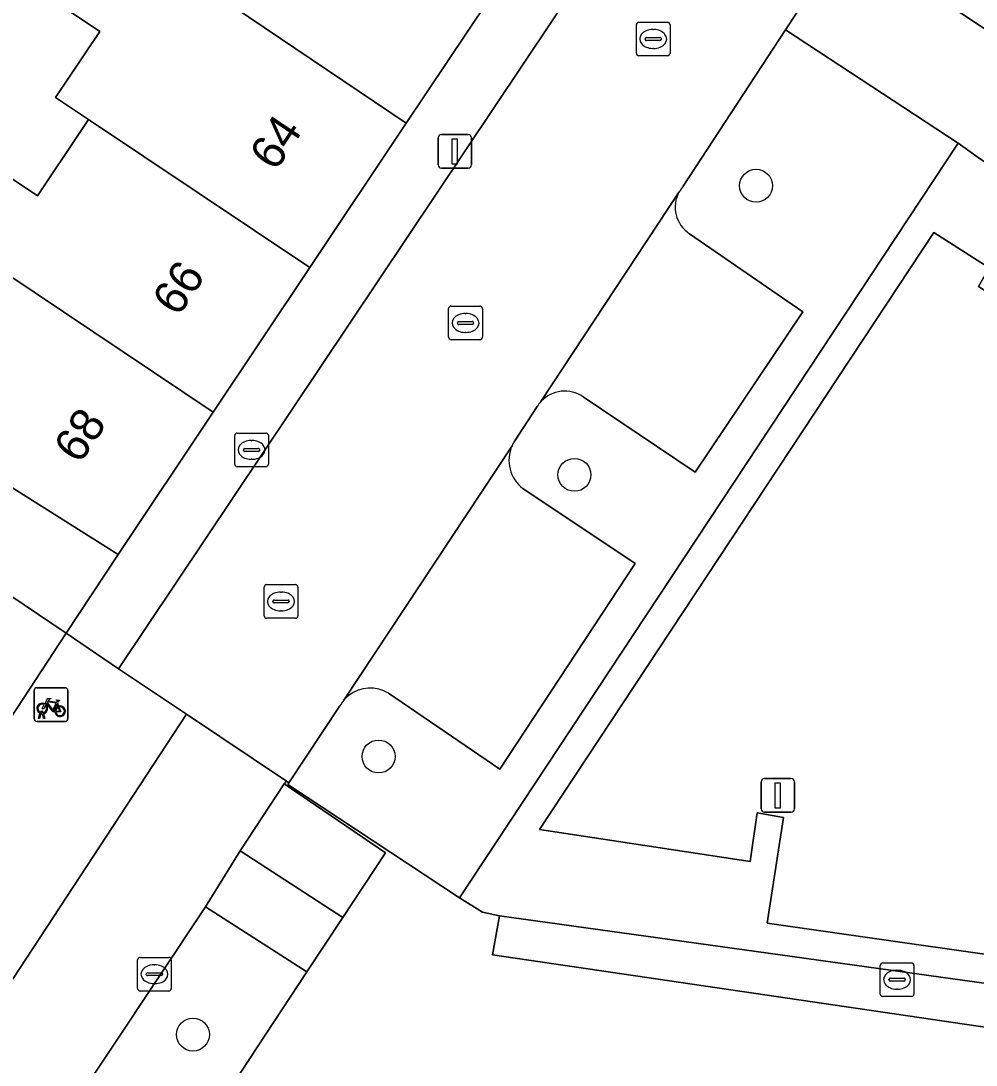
# Model space of a CAD drawing. Extents: x 159279 to 160377, y 384531 to 385888.
# Drawn here: x 159929.07 to 159957.43, y 384726.45 to 384757.45 of the extents above; entities that cross this region are included whole.
import ezdxf

# ---------------------------------------------------------------- set-up
doc = ezdxf.new("R2010")
doc.units = 0
for name, color, linetype in [('IMGEO_Boom', 7, 'Continuous'), ('IMGEO_Brandkraan', 7, 'Continuous'), ('IMGEO_Erf', 7, 'Continuous'), ('IMGEO_Fietsenrek', 7, 'Continuous'), ('IMGEO_Groenvoorziening', 7, 'Continuous'), ('IMGEO_Kolk', 7, 'Continuous'), ('IMGEO_Lichtmast', 7, 'Continuous'), ('IMGEO_Pand', 7, 'Continuous'), ('IMGEO_Pand_nummerreeks', 7, 'Continuous'), ('IMGEO_Parkeervlak_open', 7, 'Continuous'), ('IMGEO_Rijbaan_lokaal_open', 7, 'Continuous'), ('IMGEO_Terreindeel_gesloten', 7, 'Continuous'), ('IMGEO_Voetpad_halfverhard', 7, 'Continuous'), ('IMGEO_Voetpad_open', 7, 'Continuous')]:
    doc.layers.add(name, color=color, linetype=linetype)

msp = doc.modelspace()

# ---------------------------------------------------------------- linework, layer by layer
at = {"layer": 'IMGEO_Boom'}
for centre in [(159950.897, 384752.557), (159945.504, 384743.972), (159939.689, 384735.609), (159934.177, 384727.353)]:
    msp.add_circle(centre, 0.489, dxfattribs=at)
at = {"layer": 'IMGEO_Brandkraan'}
for p, q in [((159935.415, 384744.287), (159935.415, 384745.139)), ((159935.49, 384745.213), (159936.342, 384745.213)), ((159936.416, 384745.139), (159936.416, 384744.287)), ((159935.903, 384744.993), (159935.928, 384744.993)), ((159935.674, 384744.707), (159935.674, 384744.719)), ((159936.112, 384744.67), (159935.714, 384744.67)), ((159935.717, 384744.756), (159936.115, 384744.756)), ((159936.158, 384744.719), (159936.158, 384744.707)), ((159936.342, 384744.213), (159935.49, 384744.213)), ((159935.926, 384744.433), (159935.901, 384744.433))]:
    msp.add_line(p, q, dxfattribs=at)
for points in [[(159935.415, 384744.287), (159935.415, 384745.139)], [(159935.49, 384745.213), (159936.342, 384745.213)], [(159936.416, 384745.139), (159936.416, 384744.287)], [(159936.342, 384744.213), (159935.49, 384744.213)]]:
    msp.add_lwpolyline(points, dxfattribs=at)
for centre, radius, start, end in [((159935.492, 384745.137), 0.0765, 91.552, 178.448), ((159935.492, 384745.137), 0.0765, 91.552, 178.448), ((159936.34, 384745.137), 0.0765, 1.552, 88.448), ((159936.34, 384745.137), 0.0765, 1.552, 88.448), ((159935.714, 384744.716), 0.0403, 85.8775, 175.7526), ((159935.711, 384744.706), 0.0366, 178.938, 274.7102), ((159936.115, 384744.713), 0.043, 264.8664, 352.4533), ((159936.119, 384744.718), 0.0386, 1.7309, 96.639), ((159935.492, 384744.289), 0.0765, 181.552, 268.448), ((159935.492, 384744.289), 0.0765, 181.552, 268.448), ((159936.34, 384744.289), 0.0765, 271.552, 358.448), ((159936.34, 384744.289), 0.0765, 271.552, 358.448)]:
    msp.add_arc(centre, radius, start, end, dxfattribs=at)
for centre, major_axis, ratio, start_param, end_param in [((159935.902, 384744.713), (-0.387, 0.002), 0.722429, 4.712389, 7.853982), ((159935.927, 384744.713), (-0.39, 0.002), 0.717154, 1.570796, 4.712389)]:
    msp.add_ellipse(centre, major_axis=major_axis, ratio=ratio, start_param=start_param, end_param=end_param, dxfattribs=at)
at = {"layer": 'IMGEO_Erf'}
msp.add_lwpolyline([(159931.409, 384757.133), (159928.152, 384759.312), (159929.734, 384761.676), (159925.251, 384764.675), (159921.503, 384759.224), (159924.063, 384757.463), (159921.965, 384754.412), (159920.089, 384751.684), (159917.528, 384753.444), (159916.375, 384751.767), (159925.299, 384745.796), (159926.834, 384748.091), (159924.232, 384749.832), (159924.344, 384750), (159925.647, 384751.947), (159927.001, 384753.97), (159929.561, 384752.256), (159930.858, 384754.194), (159931.076, 384754.52), (159930.098, 384755.174)], close=True, dxfattribs=at)
at = {"layer": 'IMGEO_Fietsenrek'}
for p, q in [((159929.462, 384736.726), (159929.462, 384737.567)), ((159929.462, 384737.567), (159929.462, 384736.726)), ((159929.537, 384737.651), (159930.378, 384737.651)), ((159930.378, 384737.651), (159929.537, 384737.651)), ((159930.462, 384737.576), (159930.462, 384736.735)), ((159930.462, 384736.735), (159930.462, 384737.576)), ((159930.149, 384737.2), (159930.185, 384737.105)), ((159929.589, 384736.735), (159929.628, 384736.895)), ((159929.623, 384736.735), (159929.589, 384736.735)), ((159929.658, 384736.883), (159929.623, 384736.735)), ((159929.7, 384736.907), (159929.699, 384736.911)), ((159929.741, 384736.735), (159929.707, 384736.877)), ((159929.731, 384736.918), (159929.732, 384736.911)), ((159929.739, 384736.881), (159929.774, 384736.735)), ((159929.774, 384736.735), (159929.741, 384736.735)), ((159930.387, 384736.651), (159929.546, 384736.651)), ((159929.546, 384736.651), (159930.387, 384736.651))]:
    msp.add_line(p, q, dxfattribs=at)
for points in [[(159929.796, 384737.125), (159929.744, 384737.035), (159929.704, 384737.01), (159929.705, 384737.057), (159929.76, 384737.151)], [(159929.775, 384737.177), (159929.87, 384737.341), (159929.956, 384737.327), (159929.958, 384737.318), (159929.902, 384737.307), (159929.875, 384737.262), (159930.131, 384737.221)], [(159930.071, 384736.933), (159930.021, 384736.933), (159929.83, 384737.184), (159929.811, 384737.152)], [(159930.118, 384737.196), (159929.861, 384737.237), (159929.844, 384737.208), (159930.011, 384736.988), (159930.118, 384737.196)], [(159930.166, 384737.098), (159930.136, 384737.175), (159930.027, 384736.957), (159930.07, 384736.957)], [(159930.1, 384736.957), (159930.22, 384736.956), (159930.176, 384737.07)], [(159930.196, 384737.077), (159930.251, 384736.932), (159930.101, 384736.932)], [(159930.131, 384737.221), (159930.156, 384737.27), (159930.15, 384737.274), (159930.127, 384737.278), (159930.115, 384737.285), (159930.114, 384737.288), (159930.116, 384737.293), (159930.211, 384737.278), (159930.213, 384737.268), (159930.203, 384737.255), (159930.191, 384737.249), (159930.177, 384737.255), (159930.149, 384737.2)]]:
    msp.add_lwpolyline(points, dxfattribs=at)
for centre, radius, start, end in [((159929.54, 384737.573), 0.0779, 92.4484, 184.2845), ((159929.54, 384737.573), 0.0779, 92.4484, 184.2845), ((159930.384, 384737.573), 0.0779, 2.4484, 94.2845), ((159930.384, 384737.573), 0.0779, 2.4484, 94.2845), ((159929.702, 384737.036), 0.159, 62.6766, 242.1369), ((159929.702, 384737.036), 0.129, 63.3192, 238.903), ((159929.702, 384737.036), 0.129, 283.6043, 43.4302), ((159929.702, 384737.036), 0.159, 283.5766, 46.6042), ((159930.229, 384736.952), 0.159, 113.3408, 178.3217), ((159930.229, 384736.952), 0.159, 187.0065, 105.7708), ((159930.229, 384736.952), 0.129, 113.923, 177.9556), ((159930.229, 384736.952), 0.129, 188.6715, 104.5883), ((159929.682, 384736.907), 0.0499, 12.8025, 158.6934), ((159929.702, 384737.036), 0.159, 253.9967, 271.7867), ((159929.682, 384736.907), 0.0174, 12.8025, 163.4502), ((159929.702, 384737.036), 0.129, 253.415, 269.0204), ((159930.384, 384736.729), 0.0779, 272.4484, 4.2845), ((159930.384, 384736.729), 0.0779, 272.4484, 4.2845), ((159929.54, 384736.729), 0.0779, 182.4484, 274.2845), ((159929.54, 384736.729), 0.0779, 182.4484, 274.2845)]:
    msp.add_arc(centre, radius, start, end, dxfattribs=at)
at = {"layer": 'IMGEO_Groenvoorziening'}
for points in [[(159955.812, 384763.287), (159953.587, 384759.934), (159958.69, 384756.557), (159962.846, 384762.885)], [(159938.541, 384737.112), (159937.027, 384734.829), (159936.995, 384734.781), (159942.094, 384731.412), (159956.896, 384753.818), (159951.777, 384757.185)], [(159951.777, 384757.185), (159948.735, 384752.544)], [(159948.924, 384751.13), (159952.283, 384748.815), (159949.094, 384744.053), (159945.763, 384746.288)], [(159944.399, 384746.002), (159943.712, 384744.95)], [(159943.976, 384743.569), (159947.309, 384741.341), (159943.292, 384735.229), (159939.985, 384737.485)]]:
    msp.add_lwpolyline(points, dxfattribs=at)
msp.add_lwpolyline([(159966.522, 384746.486), (159959.45, 384751.12), (159958.14, 384749.162), (159957.503, 384749.564), (159957.82, 384750.117), (159956.173, 384751.172), (159944.466, 384733.445), (159950.723, 384732.487), (159950.929, 384733.935), (159951.709, 384733.802), (159951.231, 384730.665), (159961.148, 384729.249), (159961.639, 384732.366), (159964.371, 384731.982)], close=True, dxfattribs=at)
for centre, radius, start, end in [((159949.39, 384751.952), 0.883, 137.8824, 151.3636), ((159949.434, 384751.918), 0.938, 150.8226, 237.0549), ((159945.217, 384745.499), 0.96, 55.3092, 137.3611), ((159945.176, 384745.526), 0.911, 136.8762, 148.5159), ((159944.615, 384744.407), 1.054, 156.0771, 232.6552), ((159944.528, 384744.454), 0.955, 148.728, 156.5722), ((159939.365, 384736.695), 0.92, 127.8458, 140.5627), ((159939.438, 384736.623), 1.021, 57.6004, 128.5877), ((159939.492, 384736.585), 1.087, 140.3429, 151.0194)]:
    msp.add_arc(centre, radius, start, end, dxfattribs=at)
at = {"layer": 'IMGEO_Kolk'}
for p, q in [((159947.343, 384756.488), (159947.343, 384757.34)), ((159947.418, 384757.414), (159948.27, 384757.414)), ((159947.831, 384757.194), (159947.856, 384757.194)), ((159948.344, 384757.34), (159948.344, 384756.488)), ((159947.602, 384756.908), (159947.602, 384756.92)), ((159947.645, 384756.957), (159948.043, 384756.957)), ((159948.086, 384756.92), (159948.086, 384756.908)), ((159948.04, 384756.871), (159947.642, 384756.871)), ((159947.854, 384756.634), (159947.829, 384756.634)), ((159948.27, 384756.414), (159947.418, 384756.414)), ((159941.769, 384748.056), (159941.769, 384748.908)), ((159941.844, 384748.982), (159942.696, 384748.982)), ((159942.77, 384748.908), (159942.77, 384748.056)), ((159942.071, 384748.525), (159942.469, 384748.525)), ((159942.257, 384748.762), (159942.282, 384748.762)), ((159942.028, 384748.476), (159942.028, 384748.488)), ((159942.466, 384748.439), (159942.068, 384748.439)), ((159942.28, 384748.202), (159942.255, 384748.202)), ((159942.512, 384748.488), (159942.512, 384748.476)), ((159942.696, 384747.982), (159941.844, 384747.982)), ((159936.291, 384739.787), (159936.291, 384740.639)), ((159936.366, 384740.713), (159937.218, 384740.713)), ((159936.779, 384740.493), (159936.804, 384740.493)), ((159937.292, 384740.639), (159937.292, 384739.787)), ((159936.55, 384740.207), (159936.55, 384740.219)), ((159936.988, 384740.17), (159936.59, 384740.17)), ((159936.593, 384740.256), (159936.991, 384740.256)), ((159937.034, 384740.219), (159937.034, 384740.207)), ((159936.802, 384739.933), (159936.777, 384739.933)), ((159937.218, 384739.713), (159936.366, 384739.713)), ((159932.607, 384729.645), (159933.459, 384729.645)), ((159932.532, 384728.719), (159932.532, 384729.571)), ((159933.02, 384729.425), (159933.045, 384729.425)), ((159933.533, 384729.571), (159933.533, 384728.719)), ((159954.586, 384728.556), (159954.586, 384729.408)), ((159954.661, 384729.482), (159955.513, 384729.482)), ((159955.587, 384729.408), (159955.587, 384728.556)), ((159932.791, 384729.139), (159932.791, 384729.151)), ((159933.229, 384729.102), (159932.831, 384729.102)), ((159932.834, 384729.188), (159933.232, 384729.188)), ((159933.275, 384729.151), (159933.275, 384729.139)), ((159954.845, 384728.976), (159954.845, 384728.988)), ((159954.888, 384729.025), (159955.286, 384729.025)), ((159955.074, 384729.262), (159955.099, 384729.262)), ((159955.329, 384728.988), (159955.329, 384728.976)), ((159933.043, 384728.865), (159933.018, 384728.865)), ((159955.283, 384728.939), (159954.885, 384728.939)), ((159955.097, 384728.702), (159955.072, 384728.702)), ((159933.459, 384728.645), (159932.607, 384728.645)), ((159955.513, 384728.482), (159954.661, 384728.482))]:
    msp.add_line(p, q, dxfattribs=at)
for points in [[(159947.343, 384756.488), (159947.343, 384757.34)], [(159947.418, 384757.414), (159948.27, 384757.414)], [(159948.344, 384757.34), (159948.344, 384756.488)], [(159948.27, 384756.414), (159947.418, 384756.414)], [(159941.769, 384748.056), (159941.769, 384748.908)], [(159941.844, 384748.982), (159942.696, 384748.982)], [(159942.77, 384748.908), (159942.77, 384748.056)], [(159942.696, 384747.982), (159941.844, 384747.982)], [(159936.291, 384739.787), (159936.291, 384740.639)], [(159936.366, 384740.713), (159937.218, 384740.713)], [(159937.292, 384740.639), (159937.292, 384739.787)], [(159937.218, 384739.713), (159936.366, 384739.713)], [(159932.607, 384729.645), (159933.459, 384729.645)], [(159932.532, 384728.719), (159932.532, 384729.571)], [(159933.533, 384729.571), (159933.533, 384728.719)], [(159954.586, 384728.556), (159954.586, 384729.408)], [(159954.661, 384729.482), (159955.513, 384729.482)], [(159955.587, 384729.408), (159955.587, 384728.556)], [(159933.459, 384728.645), (159932.607, 384728.645)], [(159955.513, 384728.482), (159954.661, 384728.482)]]:
    msp.add_lwpolyline(points, dxfattribs=at)
for centre, radius, start, end in [((159947.42, 384757.338), 0.0765, 91.552, 178.448), ((159947.42, 384757.338), 0.0765, 91.552, 178.448), ((159948.268, 384757.338), 0.0765, 1.552, 88.448), ((159948.268, 384757.338), 0.0765, 1.552, 88.448), ((159947.642, 384756.917), 0.0403, 85.8775, 175.7526), ((159947.639, 384756.907), 0.0366, 178.938, 274.7102), ((159948.043, 384756.914), 0.043, 264.8664, 352.4533), ((159948.047, 384756.919), 0.0386, 1.7309, 96.639), ((159947.42, 384756.49), 0.0765, 181.552, 268.448), ((159947.42, 384756.49), 0.0765, 181.552, 268.448), ((159948.268, 384756.49), 0.0765, 271.552, 358.448), ((159948.268, 384756.49), 0.0765, 271.552, 358.448), ((159941.846, 384748.906), 0.0765, 91.552, 178.448), ((159941.846, 384748.906), 0.0765, 91.552, 178.448), ((159942.694, 384748.906), 0.0765, 1.552, 88.448), ((159942.694, 384748.906), 0.0765, 1.552, 88.448), ((159942.068, 384748.485), 0.0403, 85.8775, 175.7526), ((159942.473, 384748.487), 0.0386, 1.7309, 96.639), ((159942.065, 384748.475), 0.0366, 178.938, 274.7102), ((159942.469, 384748.482), 0.043, 264.8664, 352.4533), ((159941.846, 384748.058), 0.0765, 181.552, 268.448), ((159941.846, 384748.058), 0.0765, 181.552, 268.448), ((159942.694, 384748.058), 0.0765, 271.552, 358.448), ((159942.694, 384748.058), 0.0765, 271.552, 358.448), ((159936.368, 384740.637), 0.0765, 91.552, 178.448), ((159936.368, 384740.637), 0.0765, 91.552, 178.448), ((159937.216, 384740.637), 0.0765, 1.552, 88.448), ((159937.216, 384740.637), 0.0765, 1.552, 88.448), ((159936.59, 384740.216), 0.0403, 85.8775, 175.7526), ((159936.587, 384740.206), 0.0366, 178.938, 274.7102), ((159936.991, 384740.213), 0.043, 264.8664, 352.4533), ((159936.995, 384740.218), 0.0386, 1.7309, 96.639), ((159936.368, 384739.789), 0.0765, 181.552, 268.448), ((159936.368, 384739.789), 0.0765, 181.552, 268.448), ((159937.216, 384739.789), 0.0765, 271.552, 358.448), ((159937.216, 384739.789), 0.0765, 271.552, 358.448), ((159932.609, 384729.569), 0.0765, 91.552, 178.448), ((159932.609, 384729.569), 0.0765, 91.552, 178.448), ((159933.457, 384729.569), 0.0765, 1.552, 88.448), ((159933.457, 384729.569), 0.0765, 1.552, 88.448), ((159954.663, 384729.406), 0.0765, 91.552, 178.448), ((159954.663, 384729.406), 0.0765, 91.552, 178.448), ((159955.511, 384729.406), 0.0765, 1.552, 88.448), ((159955.511, 384729.406), 0.0765, 1.552, 88.448), ((159932.831, 384729.148), 0.0403, 85.8775, 175.7526), ((159932.828, 384729.138), 0.0366, 178.938, 274.7102), ((159933.232, 384729.145), 0.043, 264.8664, 352.4533), ((159933.236, 384729.15), 0.0386, 1.7309, 96.639), ((159954.885, 384728.985), 0.0403, 85.8775, 175.7526), ((159955.29, 384728.987), 0.0386, 1.7309, 96.639), ((159932.609, 384728.721), 0.0765, 181.552, 268.448), ((159932.609, 384728.721), 0.0765, 181.552, 268.448), ((159933.457, 384728.721), 0.0765, 271.552, 358.448), ((159933.457, 384728.721), 0.0765, 271.552, 358.448), ((159954.882, 384728.975), 0.0366, 178.938, 274.7102), ((159955.286, 384728.982), 0.043, 264.8664, 352.4533), ((159954.663, 384728.558), 0.0765, 181.552, 268.448), ((159954.663, 384728.558), 0.0765, 181.552, 268.448), ((159955.511, 384728.558), 0.0765, 271.552, 358.448), ((159955.511, 384728.558), 0.0765, 271.552, 358.448)]:
    msp.add_arc(centre, radius, start, end, dxfattribs=at)
for centre, major_axis, ratio, start_param, end_param in [((159947.83, 384756.914), (-0.387, 0.002), 0.722429, 4.712389, 7.853982), ((159947.855, 384756.914), (-0.39, 0.002), 0.717154, 1.570796, 4.712389), ((159942.256, 384748.482), (-0.387, 0.002), 0.722429, 4.712389, 7.853982), ((159942.281, 384748.482), (-0.39, 0.002), 0.717154, 1.570796, 4.712389), ((159936.778, 384740.213), (-0.387, 0.002), 0.722429, 4.712389, 7.853982), ((159936.803, 384740.213), (-0.39, 0.002), 0.717154, 1.570796, 4.712389), ((159933.019, 384729.145), (-0.387, 0.002), 0.722429, 4.712389, 7.853982), ((159933.044, 384729.145), (-0.39, 0.002), 0.717154, 1.570796, 4.712389), ((159955.073, 384728.982), (-0.387, 0.002), 0.722429, 4.712389, 7.853982), ((159955.098, 384728.982), (-0.39, 0.002), 0.717154, 1.570796, 4.712389)]:
    msp.add_ellipse(centre, major_axis=major_axis, ratio=ratio, start_param=start_param, end_param=end_param, dxfattribs=at)
at = {"layer": 'IMGEO_Lichtmast'}
for p, q in [((159941.457, 384753.177), (159941.457, 384753.977)), ((159941.457, 384753.977), (159941.457, 384753.177)), ((159941.557, 384754.077), (159942.347, 384754.077)), ((159942.347, 384754.077), (159941.557, 384754.077)), ((159942.447, 384753.977), (159942.447, 384753.177)), ((159942.447, 384753.177), (159942.447, 384753.977)), ((159942.347, 384753.077), (159941.557, 384753.077)), ((159941.557, 384753.077), (159942.347, 384753.077)), ((159951.149, 384734.954), (159951.939, 384734.954)), ((159951.939, 384734.954), (159951.149, 384734.954)), ((159951.049, 384734.054), (159951.049, 384734.854)), ((159951.049, 384734.854), (159951.049, 384734.054)), ((159952.039, 384734.854), (159952.039, 384734.054)), ((159952.039, 384734.054), (159952.039, 384734.854)), ((159951.939, 384733.954), (159951.149, 384733.954)), ((159951.149, 384733.954), (159951.939, 384733.954))]:
    msp.add_line(p, q, dxfattribs=at)
for points in [[(159941.877, 384753.952), (159942.027, 384753.952), (159942.027, 384753.202), (159941.877, 384753.202), (159941.877, 384753.952)], [(159951.469, 384734.829), (159951.619, 384734.829), (159951.619, 384734.079), (159951.469, 384734.079), (159951.469, 384734.829)]]:
    msp.add_lwpolyline(points, dxfattribs=at)
for centre, start, end in [((159941.557, 384753.977), 90, 180), ((159941.557, 384753.977), 90, 180), ((159942.347, 384753.977), 0, 90), ((159942.347, 384753.977), 360, 90), ((159941.557, 384753.177), 180, 270), ((159941.557, 384753.177), 180, 270), ((159942.347, 384753.177), 270, 0), ((159942.347, 384753.177), 270, 0), ((159951.149, 384734.854), 90, 180), ((159951.149, 384734.854), 90, 180), ((159951.939, 384734.854), 0, 90), ((159951.939, 384734.854), 360, 90), ((159951.149, 384734.054), 180, 270), ((159951.149, 384734.054), 180, 270), ((159951.939, 384734.054), 270, 0), ((159951.939, 384734.054), 270, 0)]:
    msp.add_arc(centre, 0.1, start, end, dxfattribs=at)
at = {"layer": 'IMGEO_Pand'}
for points in [[(159928.216, 384769.226), (159925.251, 384764.675), (159929.734, 384761.676), (159940.51, 384754.414), (159943.565, 384758.989), (159941.948, 384760.067), (159928.533, 384769.015)], [(159929.734, 384761.676), (159928.152, 384759.312), (159931.409, 384757.133), (159930.098, 384755.174), (159931.076, 384754.52), (159937.646, 384750.125), (159940.51, 384754.414)], [(159931.076, 384754.52), (159930.858, 384754.194), (159929.561, 384752.256), (159927.001, 384753.97), (159925.647, 384751.947), (159928.556, 384750), (159934.781, 384745.835), (159937.646, 384750.125)], [(159928.556, 384750), (159925.647, 384751.947), (159924.344, 384750), (159924.232, 384749.832), (159926.834, 384748.091), (159925.299, 384745.796), (159931.956, 384741.604), (159934.781, 384745.835)], [(159930.407, 384739.267), (159922.981, 384744.275), (159914.143, 384750), (159912.988, 384750.763), (159912.477, 384750), (159904.451, 384738.006), (159920.151, 384727.708), (159922.006, 384726.456)]]:
    msp.add_lwpolyline(points, close=True, dxfattribs=at)
at = {"layer": 'IMGEO_Parkeervlak_open'}
for points in [[(159948.615, 384752.375), (159944.511, 384746.149)], [(159945.763, 384746.288), (159949.094, 384744.053), (159952.283, 384748.815), (159948.924, 384751.13)], [(159943.652, 384744.834), (159938.655, 384737.279)], [(159939.985, 384737.485), (159943.292, 384735.229), (159947.309, 384741.341), (159943.976, 384743.569)]]:
    msp.add_lwpolyline(points, dxfattribs=at)
for centre, radius, start, end in [((159949.434, 384751.918), 0.938, 150.8226, 237.0549), ((159945.217, 384745.499), 0.96, 55.3092, 137.3611), ((159944.615, 384744.407), 1.054, 156.0771, 232.6552), ((159939.365, 384736.695), 0.92, 127.8458, 140.5627), ((159939.438, 384736.623), 1.021, 57.6004, 128.5877)]:
    msp.add_arc(centre, radius, start, end, dxfattribs=at)
at = {"layer": 'IMGEO_Rijbaan_lokaal_open'}
for points in [[(159948.735, 384752.544), (159951.777, 384757.185), (159953.587, 384759.934), (159955.812, 384763.287)], [(159945.68, 384758.724), (159931.969, 384738.216), (159933.985, 384736.865), (159936.955, 384734.874), (159937.027, 384734.829), (159938.541, 384737.112)], [(159944.511, 384746.149), (159948.615, 384752.375)], [(159943.712, 384744.95), (159944.399, 384746.002)], [(159938.655, 384737.279), (159943.652, 384744.834)]]:
    msp.add_lwpolyline(points, dxfattribs=at)
msp.add_lwpolyline([(159930.327, 384724.79), (159934.544, 384731.143), (159935.583, 384732.811), (159936.881, 384734.801), (159936.955, 384734.874), (159933.985, 384736.865), (159921.905, 384718.465), (159924.938, 384716.512), (159929.288, 384723.232)], close=True, dxfattribs=at)
for centre, radius, start, end in [((159949.39, 384751.952), 0.883, 137.8824, 151.3636), ((159945.176, 384745.526), 0.911, 136.8762, 148.5159), ((159944.528, 384744.454), 0.955, 148.728, 156.5722), ((159939.492, 384736.585), 1.087, 140.3429, 151.0194)]:
    msp.add_arc(centre, radius, start, end, dxfattribs=at)
at = {"layer": 'IMGEO_Terreindeel_gesloten'}
for points in [[(159956.896, 384753.818), (159942.094, 384731.412), (159942.778, 384730.989), (159943.276, 384730.876), (159964.717, 384727.899), (159967.511, 384746.78), (159957.568, 384753.343)], [(159956.173, 384751.172), (159957.82, 384750.117), (159957.503, 384749.564), (159958.14, 384749.162), (159959.45, 384751.12), (159966.522, 384746.486), (159964.371, 384731.982), (159961.639, 384732.366), (159961.148, 384729.249), (159951.231, 384730.665), (159951.709, 384733.802), (159950.929, 384733.935), (159950.723, 384732.487), (159944.466, 384733.445)]]:
    msp.add_lwpolyline(points, close=True, dxfattribs=at)
at = {"layer": 'IMGEO_Voetpad_halfverhard'}
for points in [[(159936.881, 384734.801), (159935.583, 384732.811), (159938.623, 384730.829), (159939.891, 384732.753)], [(159937.56, 384729.215), (159934.544, 384731.143), (159930.327, 384724.79), (159933.412, 384722.915)]]:
    msp.add_lwpolyline(points, close=True, dxfattribs=at)
at = {"layer": 'IMGEO_Voetpad_open'}
for points in [[(159969.518, 384784.029), (159965.512, 384778.023), (159970.581, 384774.664), (159962.846, 384762.885), (159969.196, 384758.743), (159967.965, 384750.5), (159958.69, 384756.557), (159953.587, 384759.934), (159951.777, 384757.185), (159956.896, 384753.818), (159957.568, 384753.343), (159967.511, 384746.78), (159964.717, 384727.899), (159964.504, 384726.574), (159963.831, 384722.298)], [(159943.565, 384758.989), (159940.51, 384754.414), (159937.646, 384750.125), (159934.781, 384745.835), (159931.956, 384741.604), (159930.407, 384739.267), (159931.969, 384738.216), (159945.68, 384758.724)], [(159922.981, 384744.275), (159930.407, 384739.267), (159931.956, 384741.604), (159925.299, 384745.796)], [(159963.831, 384722.298), (159964.504, 384726.574), (159943.075, 384729.724), (159943.276, 384730.876), (159942.778, 384730.989), (159942.094, 384731.412), (159936.995, 384734.781), (159937.027, 384734.829), (159936.955, 384734.874), (159936.881, 384734.801), (159939.891, 384732.753), (159938.623, 384730.829), (159937.56, 384729.215), (159933.412, 384722.915)]]:
    msp.add_lwpolyline(points, dxfattribs=at)
for points in [[(159933.985, 384736.865), (159931.969, 384738.216), (159930.407, 384739.267), (159922.006, 384726.456), (159918.252, 384720.836), (159921.905, 384718.465)], [(159935.583, 384732.811), (159934.544, 384731.143), (159937.56, 384729.215), (159938.623, 384730.829)], [(159943.276, 384730.876), (159943.075, 384729.724), (159964.504, 384726.574), (159964.717, 384727.899)]]:
    msp.add_lwpolyline(points, close=True, dxfattribs=at)

# ---------------------------------------------------------------- texts
at = {"layer": 'IMGEO_Pand_nummerreeks'}
for s, rotation, p in [('64', 56.2186, (159936.63, 384752.957)), ('66', 56.2243, (159933.741, 384748.639)), ('68', 56.2186, (159930.813, 384744.263))]:
    msp.add_text(s, height=1, rotation=rotation, dxfattribs=at).set_placement(p)

doc.saveas('drawing.dxf')
